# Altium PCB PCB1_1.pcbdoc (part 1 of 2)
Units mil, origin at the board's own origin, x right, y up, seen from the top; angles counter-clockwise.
Board outline 2585 x 2710 mil, 2 copper layers (Top Layer, Bottom Layer); 39 components, 30 nets, 170 pads, 81 vias.
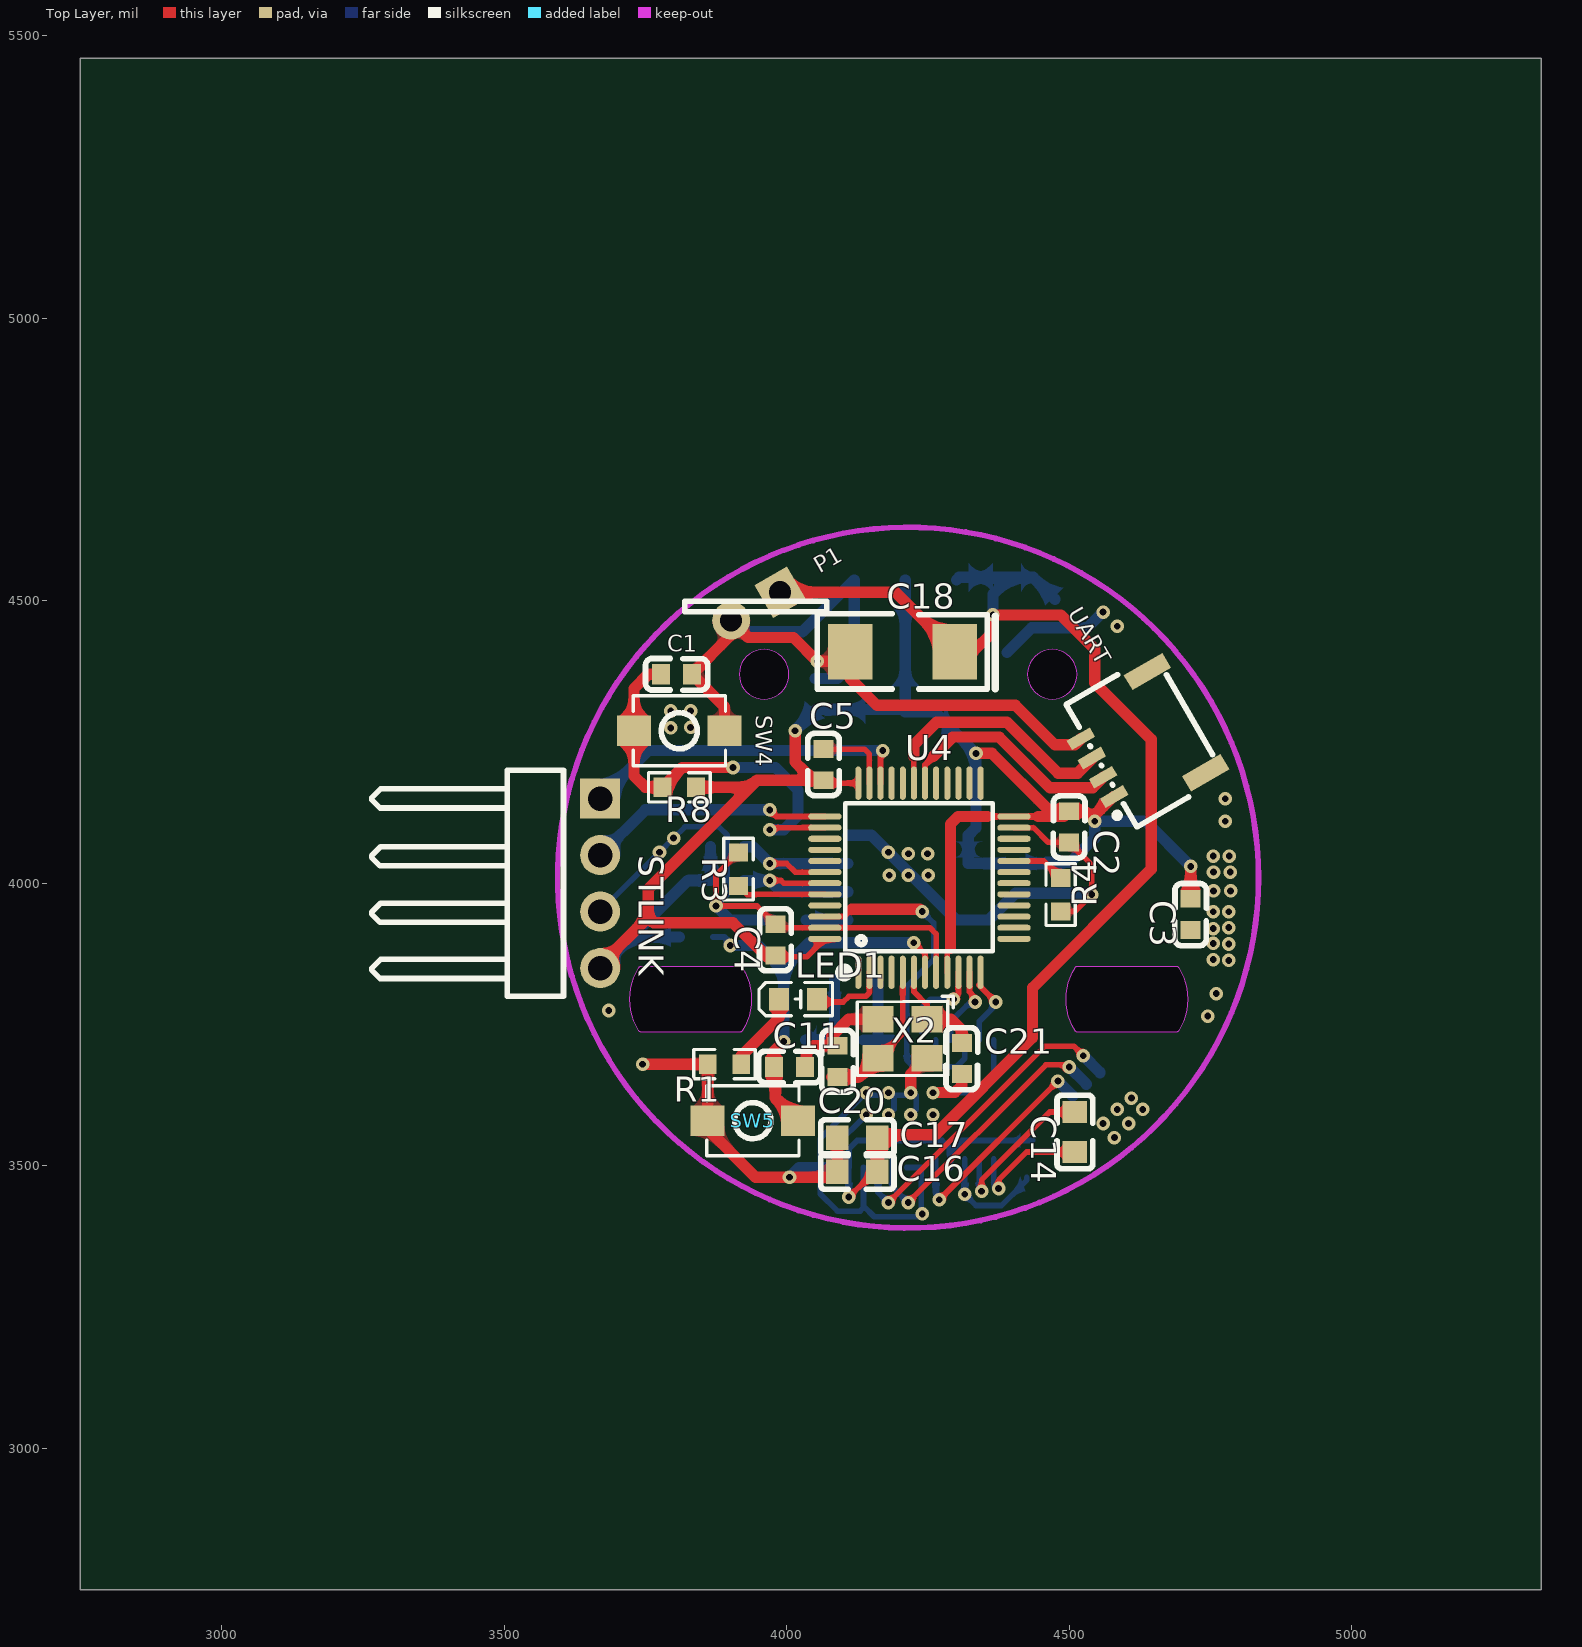
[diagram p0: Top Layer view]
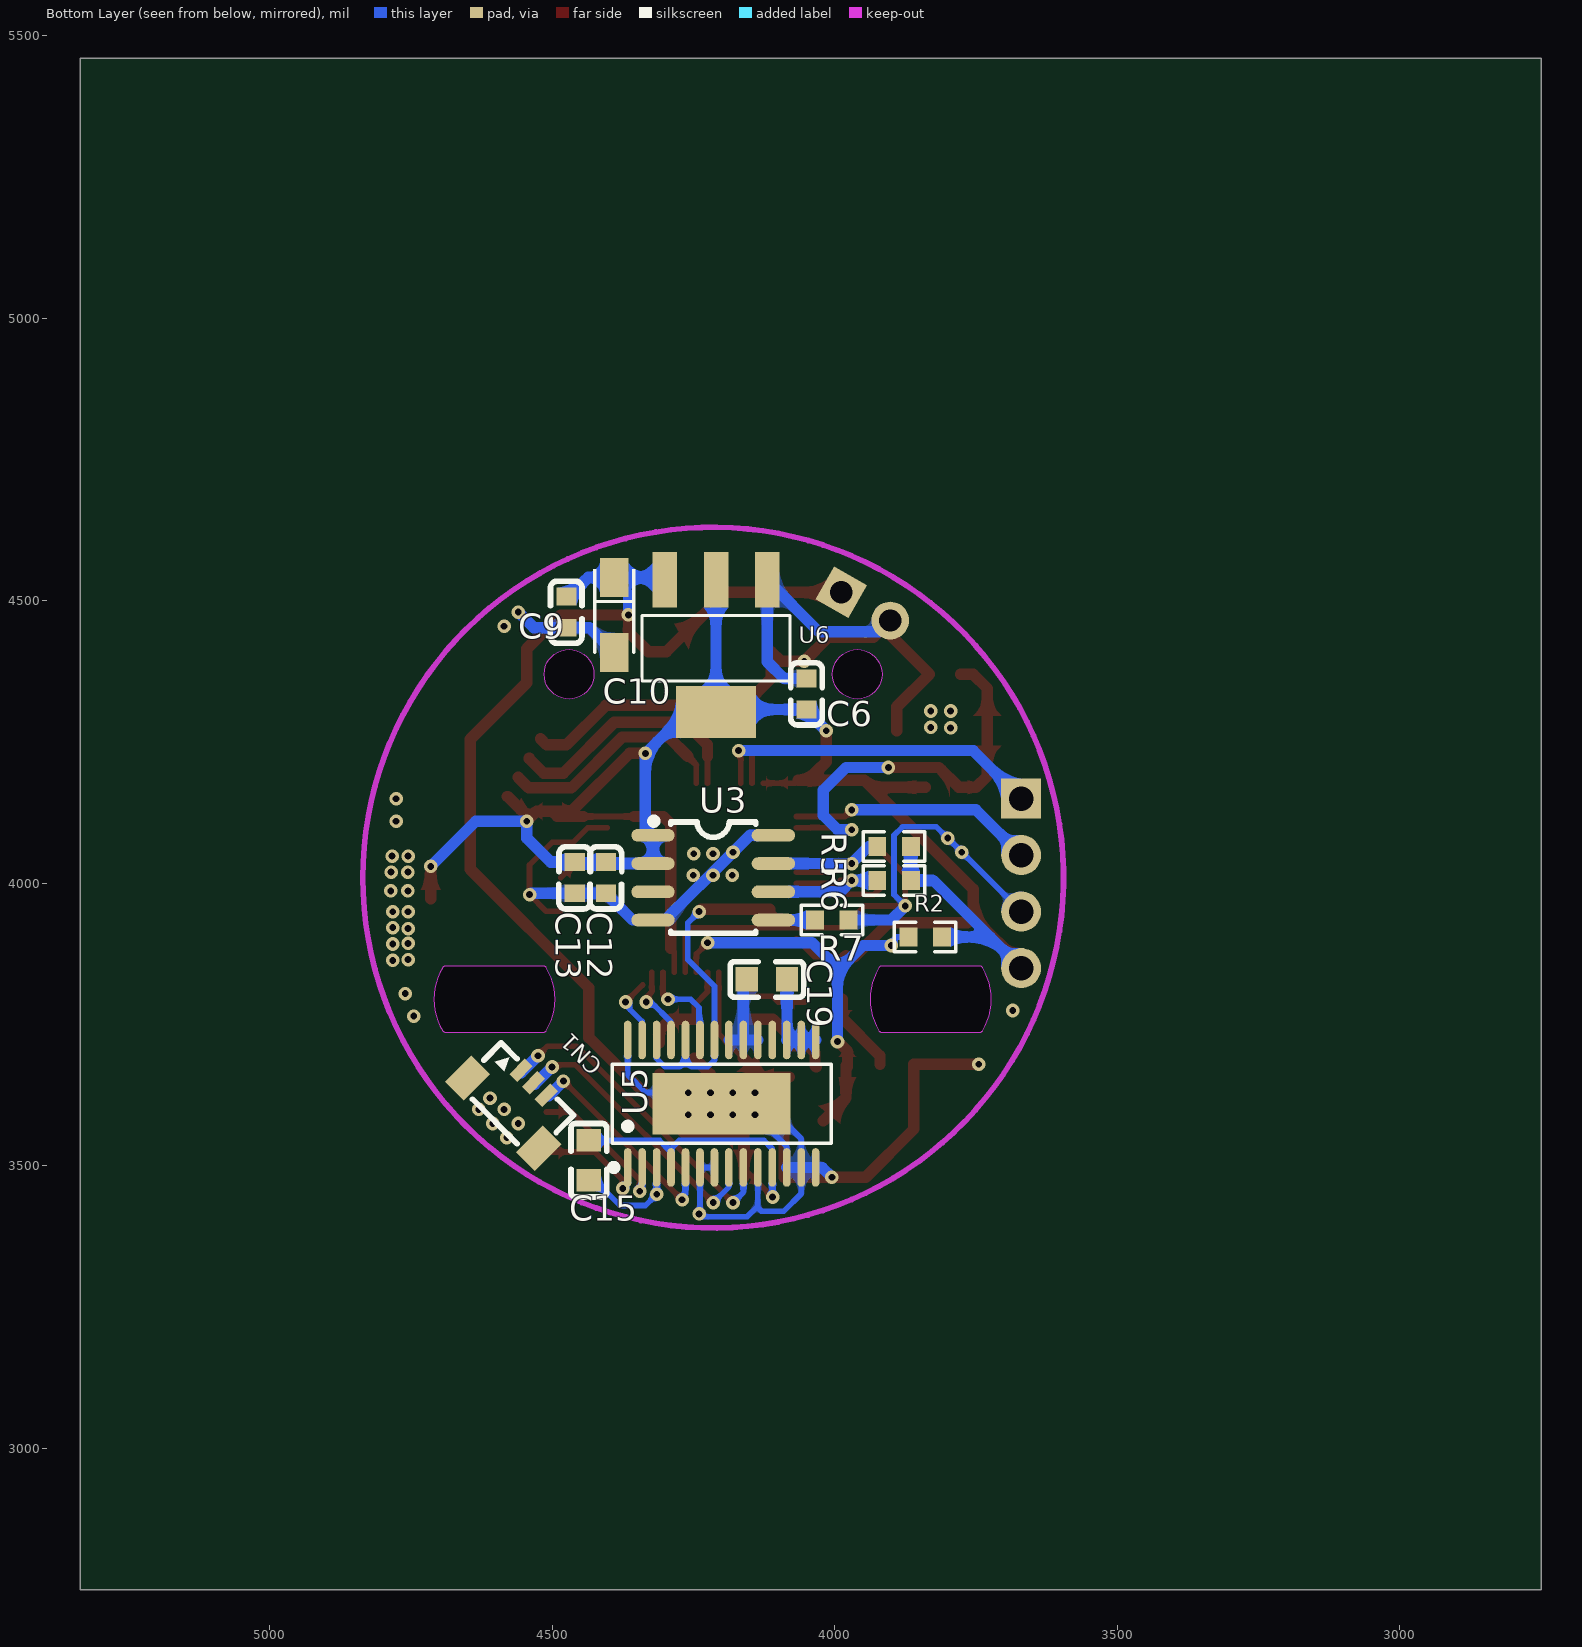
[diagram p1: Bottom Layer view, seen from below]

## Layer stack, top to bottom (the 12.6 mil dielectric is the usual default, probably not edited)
Top Layer: signal copper (thickness not stored)
Dielectric: dielectric 12.6, FR-4, Dk 4.8
Bottom Layer: signal copper (thickness not stored)

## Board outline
5335,2750 2750,2750 2750,5460 5335,5460
cut-out: 4004,4370 ccw(c3960,4370) 3916,4370 ccw(c3960,4370)
cut-out: 4514,4370 ccw(c4470,4370) 4426,4370 ccw(c4470,4370)
cut-out: 4693.77,3739.25 cw(c4689.5,3741.85) 4689.5,3736.85 4514.53,3736.85 cw(c4514.53,3741.85) 4510.26,3739.25 cw(c4602.02,3795) 4494.65,3795 cw(c4602.02,3795) 4510.26,3850.75 cw(c4514.53,3848.15) 4514.53,3853.15 4689.5,3853.15 cw(c4689.5,3848.15) 4693.77,3850.75 cw(c4602.02,3795) 4709.38,3795 cw(c4602.02,3795)
cut-out: 3921.76,3739.25 cw(c3917.48,3741.85) 3917.48,3736.85 3742.52,3736.85 cw(c3742.52,3741.85) 3738.24,3739.25 cw(c3830,3795) 3722.64,3795 cw(c3830,3795) 3738.24,3850.75 cw(c3742.52,3848.15) 3742.52,3853.15 3917.48,3853.15 cw(c3917.48,3848.15) 3921.76,3850.75 cw(c3830,3795) 3937.36,3795 cw(c3830,3795)

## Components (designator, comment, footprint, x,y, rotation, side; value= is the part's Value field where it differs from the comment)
C1 "0603F105M160NT" C0603#1 3805,4370 r180 top
C2 "0603F105M160NT" C0603#1 4500,4100 r90 top
C3 "0603F105M160NT" C0603#1 4715,3945 r90 top
C4 "0603F105M160NT" C0603#1 3980,3900 r270 top
C5 "0603F105M160NT" C0603#1 4065,4210 r270 top
C6 "0.1uf" C0603#1 4050,4335 r270 bottom
C9 "0.1uf" C0603#1 4475,4480 r90 bottom
C10 "10uF" CAP-SMD_L3.2-W1.6-RD 4390,4475 r270 bottom
C11 "0603F105M160NT" C0603#1 4005,3675 r180 top
C12 "0.1uf" C0603#1 4405,4010 r90 bottom
C13 "1uf" C0603#1 4460,4010 r90 bottom
C14 "0.01uF" C0603#2 4510,3560 r270 top
C15 "0.1uF" C0603#2 4435,3510 r270 bottom
C16 "0.1uF" C0603#2 4125,3490 r180 top
C17 "0.1uF" C0603#2 4125,3550 r0 top
C18 "100uF" CAP-SMD_L6.0-W3.2-R-RD 4205,4410 r0 top
C19 "0.47uF" C0603#2 4120,3830 r0 bottom
C20 "0603CG200J101NT" C0603#1 4090,3685 r270 top
C21 "0603CG200J101NT" C0603#1 4310,3690 r90 top
CN1 "X0800WRS-03HF-LPV01" CONN-SMD_X0800WRS-03HF-LPV01 4560,3620 r225 bottom
LED1 "FC-DA1608HRK-620D" LED0603-FD 4020,3795 r180 top
P1 "2.54-1*2P母" HDR-TH_2P-P2.54-V-F 3945,4490 r210 top
R1 "510Ω" R0603 3890,3680 r0 top
R2 "HoLTT0603-1/10W-100KR-1%" R0603 3840,3905 r180 bottom
R3 "10k" R0603 3915,4025 r90 top
R4 "10k" R0603 4485,3980 r90 top
R5 "10k" R0603 3895,4065 r180 bottom
R6 "10k" R0603 3895,4005 r180 bottom
R7 "1k" R0603 4005,3935 r0 bottom
R8 "HoLTT0603-1/10W-100KR-1%" R0603 3810,4170 r0 top
STLINK "2.54-1*4P反弯排针" HDR-TH_4P-P2.54-H-M-W10.4 3670,4000 r270 top
SW4 "KEY-3*4*2" SW-SMD_L4.0-W2.9-LS5.0 3810,4270 r180 top
SW5 "KEY-3*4*2" SW-SMD_L4.0-W2.9-LS5.0 3940,3580 r0 top
U3 "AS5600" SOIC-8_L5.0-W4.0-P1.27-LS6.0-BL 4215,4010 r270 bottom
U4 "STM32F103C8T6" LQFP-48_L7.0-W7.0-P0.50-LS9.0-BL 4235,4010 r0 top
U5 "DRV8313PWPR" HTSSOP-28_L9.8-W4.5-P0.65-LS6.6-BL-EP 4200,3610 r180 bottom
U6 "AMS1117-3.3_C6186" SOT-223-3_L6.5-W3.4-P2.30-LS7.0-BR 4210,4420 r90 bottom
UART "HDGC1002WR-S-4P" CONN-SMD_4P-P1.00_HDGC_HDGC1002WR-S-4P 4620,4245 r120 top
X2 "3225-8.00-10-10-10/A" OSC-SMD_4P-L3.2-W2.5-BL 4205,3725 r180 top

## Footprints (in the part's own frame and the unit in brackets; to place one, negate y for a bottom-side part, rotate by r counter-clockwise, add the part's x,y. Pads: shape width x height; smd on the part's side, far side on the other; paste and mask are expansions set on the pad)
C0603#1 [mm]
  rect 0.8x0.9 smd: 1(-0.7,0) 2(0.7,0)
  silkscreen extent -1.41,-0.71 1.39,0.72
C0603#2 [mm]
  rect 1x1.1 smd: 1(-0.9,0) 2(0.9,0)
  silkscreen extent -1.65,-0.8 1.65,0.8
CAP-SMD_L3.2-W1.6-RD [mil]
  rect 69.19x51.02 smd: 1(-66.39,0) 2(66.39,0)
  silkscreen extent -81,-37 66,37
CAP-SMD_L6.0-W3.2-R-RD [mm]
  rect 2x2.5 smd: 1(2.35,0) 2(-2.35,0)
  silkscreen extent -3.84,-1.68 4.17,1.7
CONN-SMD_4P-P1.00_HDGC_HDGC1002WR-S-4P [mm]
  rect 0.5x1.2 smd: 1(-1.5,2.05) 2(-0.5,2.05) 3(0.5,2.05) 4(1.5,2.05)
  rect 0.8x2 smd: 5(2.625,-2.05) 6(-2.625,-2.05)
  silkscreen extent -3.18,-2.72 3.17,2.48
CONN-SMD_X0800WRS-03HF-LPV01 [mm]
  rect 0.5x1 smd: 1(-0.8,0.972) 2(0,0.972) 3(0.8,0.972)
  rect 1.2x1.7 smd: 4(2.25,-0.95) 5(-2.25,-0.972)
  silkscreen extent -2.3,-1.49 2.3,1.21
HDR-TH_2P-P2.54-V-F [mm]
  rect 1.7x1.7 hole 1: 1(-1.27,0)
  round 1.7 hole 1: 2(1.27,0)
  silkscreen extent -2.88,-1.79 2.88,1.8
HDR-TH_4P-P2.54-H-M-W10.4 [mm]
  rect 1.8x1.8 hole 1.1: 1(-3.81,0)
  round 1.8 hole 1.1: 2(-1.27,0) 3(1.27,0) 4(3.81,0)
  silkscreen extent -5.09,-10.27 5.07,-1.65
HTSSOP-28_L9.8-W4.5-P0.65-LS6.6-BL-EP [mil]
  oval 13.5x68.2 smd: 1(-166.3,-112.8) 2(-140.7,-112.8) 3(-115.2,-112.8) 4(-89.6,-112.8) 5(-64,-112.8) 6(-38.4,-112.8) 7(-12.8,-112.8) 8(12.8,-112.8) 9(38.4,-112.8) 10(64,-112.8) 11(89.6,-112.8) 12(115.2,-112.8) 13(140.8,-112.8) 14(166.3,-112.8) 15(166.3,112.8) 16(140.8,112.8) 17(115.2,112.8) 18(89.6,112.8) 19(64,112.8) 20(38.4,112.8) 21(12.8,112.8) 22(-12.8,112.8) 23(-38.4,112.8) 24(-64,112.8) 25(-89.6,112.8) 26(-115.2,112.8) 27(-140.7,112.8) 28(-166.3,112.8)
  rect 244.1x108.3 smd: 29(0,0)
  silkscreen extent -197,-119 194,70
LED0603-FD [mm]
  rect 0.9x1 smd: 1(-0.85,0) 2(0.85,0)
  silkscreen extent -1.55,-0.75 1.75,0.75
LQFP-48_L7.0-W7.0-P0.50-LS9.0-BL [mm]
  oval 0.27x1.5 smd: 1(-2.75,-4.25) 2(-2.25,-4.25) 3(-1.75,-4.25) 4(-1.25,-4.25) 5(-0.75,-4.25) 6(-0.25,-4.25) 7(0.25,-4.25) 8(0.75,-4.25) 9(1.25,-4.25) 10(1.75,-4.25) 11(2.25,-4.25) 12(2.75,-4.25) 25(2.75,4.25) 26(2.25,4.25) 27(1.75,4.25) 28(1.25,4.25) 29(0.75,4.25) 30(0.25,4.25) 31(-0.25,4.25) 32(-0.75,4.25) 33(-1.25,4.25) 34(-1.75,4.25) 35(-2.25,4.25) 36(-2.75,4.25)
  oval 1.5x0.27 smd: 13(4.25,-2.75) 14(4.25,-2.25) 15(4.25,-1.75) 16(4.25,-1.25) 17(4.25,-0.75) 18(4.25,-0.25) 19(4.25,0.25) 20(4.25,0.75) 21(4.25,1.25) 22(4.25,1.75) 23(4.25,2.25) 24(4.25,2.75) 37(-4.25,2.75) 38(-4.25,2.25) 39(-4.25,1.75) 40(-4.25,1.25) 41(-4.25,0.75) 42(-4.25,0.25) 43(-4.25,-0.25) 44(-4.25,-0.75) 45(-4.25,-1.25) 46(-4.25,-1.75) 47(-4.25,-2.25) 48(-4.25,-2.75)
  silkscreen extent -3.59,-4.46 3.3,3.34
OSC-SMD_4P-L3.2-W2.5-BL [mm]
  rect 1.4x1.2 smd: 1(-1.1,-0.875) 2(1.1,-0.875) 3(1.1,0.875) 4(-1.1,0.875)
  silkscreen extent -2.29,-1.9 2.03,1.65
R0603 [mil]
  rect 31.75x34.02 smd: 1(-29.66,0) 2(29.66,0)
  silkscreen extent -55,-26 55,26
SOIC-8_L5.0-W4.0-P1.27-LS6.0-BL [mil]
  oval 22.38x76.78 smd: 1(-75,-106.5) 2(-25,-106.5) 3(25,-106.5) 4(75,-106.5) 5(75,106.5) 6(25,106.5) 7(-25,106.5) 8(-75,106.5)
  silkscreen extent -106,-111 98,75
SOT-223-3_L6.5-W3.4-P2.30-LS7.0-BR [mm]
  rect 2.5x1.1 smd: 1(2.97,-2.3) 2(2.97,0) 3(2.97,2.3)
  rect 2.34x3.6 smd: 4(-2.97,0)
  silkscreen extent -1.57,-3.33 1.37,3.33
SW-SMD_L4.0-W2.9-LS5.0 [mm]
  rect 1.53x1.36 smd: 1(-2.035,0) 2(2.035,0)
  silkscreen extent -2.08,-1.58 2.08,1.58

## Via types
v1: diameter 24, hole 12.01, Top Layer to Bottom Layer, 73 vias
v2: diameter 23.62, hole 11.81, Top Layer to Bottom Layer, 8 vias

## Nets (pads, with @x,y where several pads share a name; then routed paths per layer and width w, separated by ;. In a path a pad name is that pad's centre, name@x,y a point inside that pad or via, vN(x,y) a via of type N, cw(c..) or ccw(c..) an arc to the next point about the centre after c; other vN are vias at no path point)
$1N6846: LED1.2 R1.2 | length 142.7
  Top Layer w20: R1.2@3919.66,3680 3919.66,3694.66 3986.53,3761.53 LED1.2@3986.53,3795
$1N8586: C14.2 U5.1 | length 226.3
  Top Layer w10: v1(4375,3460) 4375,3475 4424.56,3524.56 C14.2@4510,3524.56
  Bottom Layer w10: U5.1@4366.3,3512.2 4366.3,3468.7 v1(4375,3460)
$1N8587: C14.1 U5.2 | length 293.9
  Top Layer w10: v1(4345,3455) 4345,3475 4465.43,3595.43 C14.1@4510,3595.43
  Bottom Layer w10: U5.2@4340.7,3512.2 4340.7,3459.3 v1(4345,3455)
$1N8589: C15.2 U5.3 | length 203.8
  Bottom Layer w10: U5.3@4315.2,3512.2 4315.2,3450.2 v1(4315,3450) 4335,3430 4380,3430 4425,3475 C15.2@4425,3479.56
$1N8596: C19.1 U5.15 U5.16 U5.17 | length 158.4
  Bottom Layer w20: U5.15@4033.7,3722.8 U5.16@4059.2,3722.8 U5.17@4084.8,3722.8 4084.57,3723.03 C19.1@4084.57,3830
$1N18711: R7.2 U3.5 | length 73.8
  Bottom Layer w20: R7.2@4034.66,3935 U3.5@4108.5,3935
BOOT0: R3.1 U4.44 | length 159.2
  Top Layer w10: R3.1@3915,3995.34 3930.34,3980 3945,3980 3945.47,3980.47 U4.44@4067.68,3980.47
BOOT1: R4.2 U4.20 | length 95.1
  Top Layer w10: U4.20@4402.32,4039.53 4455.13,4039.53 R4.2@4485,4009.66
EN: U4.46 U5.22 U5.24 U5.26 | length 662.2
  Top Layer w10: U4.46@4067.68,3941.1 4102.21,3941.1 4115,3953.89
  Top Layer w20: 4115,3953.89 4236.11,3953.89 v1(4240,3950)
  Bottom Layer w10: v1(4240,3950) 4260,3930 4260,3865 4212.8,3817.8 U5.22@4212.8,3722.8 4212.8,3687.8 4212.5,3687.5 4224.87,3675.13 4253.13,3675.13 4264,3686 ; U5.24@4264,3722.8 4264,3686 ; U5.26@4315.2,3722.8 4315.2,3690.2 4300.13,3675.13 4274.87,3675.13 4264,3686
GND: C1.1 C2.1 C3.1 C4.1 C5.1 C6.1 C9.1 C10.2 C11.1 C12.1 C13.1 C16.2 C17.1 C18.2 C19.2 C20.1 C21.1 P1.2 R1.1 R3.2 R4.1 R7.1 STLINK.3 SW4.1 SW5.1 U3.4 U3.8 U4.8 U4.23 U4.35 U4.47 U5.6 U5.7 U5.10 U5.12 U5.13 U5.14 U5.19 U5.20 U5.21 U5.28 U5.29 U6.1 UART.4 X2.2 X2.4 | length 5997.2
  Top Layer w10: SW5.1@3859.88,3580 SW5.1@3860.34,3580.46 ; R3.2@3915,4054.66 3875,4014.66 v1(3875,3960) 3947.56,3960 C4.1@3980,3927.56 3986.14,3921.42 U4.47@4067.68,3921.42 4253.58,3921.42 4264.53,3910.47 U4.8@4264.53,3842.68 ; v1(4005,3480) v1@4005,3485 ; C5.1@4065,4237.56 4137.44,4237.56 4146.42,4228.58 U4.35@4146.42,4177.32 ; C16.2@4084.56,3490 4085,3489.56 C16.2@4085,3480 ; U4.23@4402.32,4098.58 4436.85,4098.58 4462.99,4072.44 C2.1@4500,4072.44 4540,4032.44 v1(4540,3980) 4510.34,3950.34 R4.1@4485,3950.34
  Top Layer w20: v1(3745,3680) R1.1@3860.34,3680 SW5.1@3860.34,3580.46 ; SW5.1@3859.88,3580 3859.88,3565.12 3945,3480 v1(4005,3480) C16.2@4085,3480 ; SW4.1@3890.12,4270 3890.12,4312.44 C1.1@3832.56,4370 3901.7,4439.14 P1.2@3901.7,4465 3931.7,4435 4011.96,4435 v1(4054,4392.96) 4095.44,4392.96 C18.2@4112.48,4410 4112.48,4362.52 4160,4315 4405,4315 4475,4245 4509.8,4245 UART.4@4520.58,4255.79 ; C11.1@4032.56,3675 4035,3677.44 4035,3700 4047.56,3712.56 4080,3712.56 4080,3730 4109.45,3759.45 X2.2@4161.69,3759.45 ; C16.2@4089.57,3480.01 C17.1@4089.57,3555 ; 4219.7,3629.7 4219.7,3661.94 X2.4@4248.31,3690.55 ; 4259,3629.7 4297.26,3629.7 4310,3642.44 C21.1@4310,3662.44
  Bottom Layer w10: STLINK.3@3670,3950 v1(3775,4055) v1(3800,4080) 3820,4100 3880,4100 3895,4085 3895,3980 v1(3875,3960) ; v1(4005,3480) v1@4005,3485 ; U5.12@4084.8,3497.2 4084.8,3534.2 U5.29@4140.9,3590.3 ; U5.10@4136,3497.2 4136,3429 ; U5.29@4140,3625 U5.29@4185,3625 ; U5.29@4140.9,3629.7 4059.2,3548 U5.13@4059.2,3497.2 4059.2,3450.8 4090,3420 4130,3420 4136,3426 4136,3429 ; U5.29@4180.3,3590.3 4190,3600 U5.29@4190,3625 ; U5.29@4180.3,3629.7 U5.29@4185,3625 ; U5.7@4212.8,3497.2 U5.6@4238.4,3497.2 4238.4,3416.6 v1(4240,3415) 4235,3410 4155,3410 4136,3429 ; U5.29@4219.7,3590.3 4229.4,3600 4229.4,3625 U5.29@4190,3625 ; U5.29@4259,3629.7 4259.3,3630 4335,3630 4366.3,3661.3 U5.28@4366.3,3722.8 ; U5.29@4185,3625 U5.29@4190,3625
  Bottom Layer w20: v1(3875,3960) 3900,3935 R7.1@3975.34,3935 ; P1.2@3901.7,4465 3921.7,4445 4027.52,4445 U6.1@4119.45,4536.93 4119.45,4392.01 4090,4362.56 C6.1@4050,4362.56 ; v1(4005,3480) 4022.2,3497.2 U5.14@4033.7,3497.2 U5.13@4059.2,3497.2 U5.12@4084.8,3497.2 ; v1@4053.47,4392.44 v1(4054,4392.96) ; U3.8@4108.5,4085 4150,4085 v1(4180,4055) 4300,3935 U3.4@4321.5,3935 4357.56,3935 C12.1@4405,3982.44 C13.1@4460,3982.44 4537.56,3982.44 v1(4540,3980) ; U5.19@4136,3722.8 U5.20@4161.6,3722.8 ; C19.2@4155.44,3830 4161.6,3823.84 U5.20@4161.6,3722.8 ; U5.21@4187.2,3722.8 U5.20@4161.6,3722.8 ; C10.2@4390,4408.61 4433.83,4452.44 C9.1@4475,4452.44 4532.44,4452.44 v1(4560,4480)
  other v1: 4580,3550 4560,3575 4605,3575 4585,3600 4630,3600 4610,3620 4745,3765 3685,3775 4760,3805 4782.13,3863.53 4755,3865 4782.13,3892.63 4755,3893.75 4755,3920 4782.13,3921.72 4755,3949.69 4782.13,3949.69 4755.28,3986.62 4785.49,3986.62 4181.39,4014.2 4215.39,4014.2 4250.4,4014.2 4755.28,4020 4785,4020 4755,4048.16 4783.25,4048.16 4215.39,4052.43 4249.38,4052.43 4776.17,4109.89 4776.17,4149.61 3795,4275 3830,4275.93 3795,4305 3830,4305 4585,4455
KEY1: C1.2 R8.1 SW4.2 U4.38 | length 746.8
  Top Layer w10: v1(3970,4095) 3973.58,4098.58 U4.38@4067.68,4098.58
  Top Layer w20: C1.2@3777.44,4370 3755,4370 3729.88,4344.88 SW4.2@3729.88,4270 3729.88,4190.12 3750,4170 R8.1@3780.34,4170 3815.34,4205 v1(3905,4205)
  Bottom Layer w20: v1(3905,4205) 3980,4205 4020,4165 4020,4120 3995,4095 v1(3970,4095)
LED: LED1.1 U4.2 | length 136
  Top Layer w10: LED1.1@4053.46,3790 4100,3790 4110,3800 4140,3800 4146.42,3806.42 U4.2@4146.42,3842.68
OSC_IN: C20.2 U4.5 X2.3 | length 265.7
  Top Layer w10: X2.3@4161.69,3690.55 4205.47,3734.33 U4.5@4205.47,3842.68
  Top Layer w20: C20.2@4080,3657.44 4128.58,3657.44 X2.3@4161.69,3690.55
OSC_OUT: C21.2 U4.6 X2.1 | length 185
  Top Layer w10: U4.6@4225.16,3842.68 4225.16,3808.15 4248.31,3785 X2.1@4248.31,3759.45
  Top Layer w20: X2.1@4248.31,3759.45 4290.55,3759.45 4310,3740 C21.2@4310,3717.56
PWM1: U4.12 U5.27 | length 121.9
  Top Layer w10: U4.12@4339.9,3820.11 v1(4370,3790)
  Bottom Layer w10: U5.27@4340.7,3722.8 4340.7,3755.7 4370,3785 v1(4370,3790)
PWM2: U4.11 U5.25 | length 147.1
  Top Layer w10: U4.11@4323.58,3842.68 4323.58,3808.15 4333.47,3798.26 v1(4333.47,3789.99)
  Bottom Layer w10: U5.25@4289.6,3722.8 4290,3723.2 4290,3755 4324.99,3789.99 v1(4333.47,3789.99)
PWM3: U4.10 U5.23 | length 155.4
  Top Layer w10: v1(4295,3795) 4303.9,3803.9 U4.10@4303.9,3842.68
  Bottom Layer w10: U5.23@4238.4,3737.8 4240,3739.4 4240,3780 4255,3795 v1(4295,3795)
RESET: C11.2 R2.1 SW5.2 U4.7 | length 759.1
  Top Layer w10: v1(4225,3895) 4244.84,3875.16 U4.7@4244.84,3842.68
  Top Layer w20: C11.2@3977.44,3675 3977.44,3703.28 3994.16,3720 v1(3995,3720) ; C11.2@3980,3677.44 3980,3620.12 SW5.2@4020.12,3580
  Bottom Layer w10: R2.1@3869.66,3905 3890,3905 3900,3895 v1(3900,3890)
  Bottom Layer w20: v1(3900,3890) 3950,3890 3995,3845 ; v1(3995,3720) 3995,3845 ; v1(4225,3895) 4040,3895 3995,3850 3995,3845
RX: U4.31 UART.3 | length 448.9
  Top Layer w10: U4.31@4225.16,4177.32 4225.16,4224.84 4225,4225 4225.16,4225
  Top Layer w20: 4225,4225 4225,4245 4265,4285 4390,4285 4480,4195 4515,4195 4540.27,4220.27 UART.3@4540.27,4221.69
SCL: R5.1 U3.7 U4.42 | length 300.2
  Top Layer w10: v1(3970,4035) 4000,4035 4015.16,4019.84 U4.42@4067.68,4019.84
  Bottom Layer w20: R5.1@3924.66,4065 3940,4065 v1(3970,4035) U3.7@4108.5,4035
SDA: R6.1 U3.6 U4.43 | length 291.9
  Top Layer w10: v1(3970,4005) 3990,4005 3995,4000 4067.52,4000 U4.43@4067.68,4000.16
  Bottom Layer w20: R6.1@3924.66,4005 v1(3970,4005) 3990,3985 U3.6@4108.5,3985
SWCLK: STLINK.2 U4.37 | length 435.7
  Top Layer w10: v1(3970,4130) 3981.73,4118.27 U4.37@4067.68,4118.27
  Bottom Layer w20: STLINK.2@3670,4050 3750,4130 v1(3970,4130)
SWDIO: STLINK.1 U4.34 | length 594.5
  Top Layer w10: U4.34@4166.1,4177.32 4166.1,4231.1 v1(4170,4235)
  Bottom Layer w20: STLINK.1@3670,4150 3755,4235 v1(4170,4235)
TX: U4.30 UART.2 | length 413
  Top Layer w10: U4.30@4244.84,4177.32 4244.84,4209.84 4260,4225
  Top Layer w20: 4260,4225 4294.02,4259.02 4375.98,4259.02 4465.98,4169.02 4541.37,4169.02 UART.2@4559.95,4187.6
U: CN1.3 U5.5 | length 408.7
  Top Layer w10: v1(4270,3440) v1(4480,3650)
  Bottom Layer w10: U5.5@4264,3512.2 4264,3450.14 4270,3444.14 v1(4270,3440)
  Bottom Layer w20: v1(4480,3650) 4505.92,3624.08 CN1.3@4506.26,3624.08
V: CN1.2 U5.8 | length 519.5
  Top Layer w10: v1(4215,3435) 4458.76,3678.76 4496.24,3678.76 v1(4500,3675)
  Bottom Layer w10: U5.8@4187.2,3512.2 4187.2,3462.8 v1(4215,3435)
  Bottom Layer w20: v1(4500,3675) 4530.39,3644.61 CN1.2@4530.39,3644.33
VCC: C9.2 C10.1 C15.1 C16.1 C17.2 C18.1 P1.1 U5.4 U5.11 U6.3 | length 2738.3
  Top Layer w10: v1(4110,3445) 4155,3490 C16.1@4160.43,3490
  Top Layer w20: P1.1@3988.3,4515 4192.52,4515 C18.1@4297.52,4410 4330,4410 4365,4445 v1(4365,4475) 4485,4475 4545,4415 4545,4355 4645,4255 4645,4025 4435,3815 4435,3726.97 4263.03,3555 4160.44,3555 C16.1@4160.44,3480.01
  Bottom Layer w10: v1(4110,3445) 4110,3496.8 U5.11@4110.4,3497.2 4110.4,3530.27 4124.98,3544.85 4275.15,3544.85 4289.6,3530.4 U5.4@4289.6,3497.2 4290,3497.6 4290,3525 4309.87,3544.87 4434.44,3544.87 C15.1@4435,3545.43
  Bottom Layer w20: U6.3@4300.55,4536.93 4305.01,4541.39 C10.1@4395,4541.39 ; v1(4365,4475) 4365,4511.39 C10.1@4395,4541.39 ; C9.2@4475,4502.56 4436.17,4541.39 C10.1@4395,4541.39
VCC3V3: C2.2 C3.2 C4.2 C5.2 C6.2 C12.2 C13.2 R2.2 R5.2 R6.2 R8.2 STLINK.4 U3.1 U3.2 U4.9 U4.24 U4.36 U4.48 U6.2 U6.4 UART.1 | length 3725.4
  Top Layer w10: C4.2@3982.56,3870 4035.95,3870 U4.48@4067.68,3901.73 ; C5.2@4065,4182.44 4070.12,4177.32 U4.36@4126.73,4177.32 ; U4.9@4284.21,3842.68 4284.21,3879.21 4290,3885 ; 4355,4118.27 U4.24@4402.32,4118.27 4445,4118.27
  Top Layer w20: STLINK.4@3670,3850 3670,3855 3755,3940 ; R8.2@3839.66,4170 3935,4170 ; C4.2@3980,3872.44 3980.12,3872.44 3982.56,3870 3965,3870 3905,3930 3765,3930 3755,3940 ; v1(4015,4270) 4015,4215 C5.2@4047.56,4182.44 ; C5.2@4065,4182.44 C5.2@4047.56,4182.44 ; 4290,3885 4290,4105 4303.27,4118.27 4355,4118.27 ; v1(4335,4230) 4363.28,4230 4465.72,4127.56 C2.2@4500,4127.56 ; 4445,4118.27 4490.71,4118.27 C2.2@4500,4127.56 ; UART.1@4579.64,4153.5 4578.5,4153.5 4545,4120 v1(4545,4110) 4527.44,4127.56 C2.2@4500,4127.56 ; C3.2@4715,3972.56 v1(4715,4030) ; 3755,3940 3755,3990 3935,4170 ; 3935,4170 3947.44,4182.44 C5.2@4047.56,4182.44
  Bottom Layer w20: STLINK.4@3670,3850 3725,3905 ; R2.2@3810.34,3905 3725,3905 ; R5.2@3865.34,4065 R6.2@3865.34,4005 3825,4005 3725,3905 ; v1(4015,4270) 4052.44,4307.44 4090,4307.44 4205.63,4307.44 U6.4@4210,4303.07 ; U6.2@4210,4536.93 U6.4@4210,4303.07 ; C13.2@4460,4032.56 4457.56,4035 U3.2@4321.5,4035 U3.1@4321.5,4085 4335,4098.5 v1(4335,4230) 4261.93,4303.07 U6.4@4210,4303.07 ; C13.2@4460,4037.56 4502.56,4037.56 4545,4080 v1(4545,4110) 4635,4110 v1(4715,4030)
W: CN1.1 U5.9 | length 594.3
  Top Layer w10: v1(4180,3435) 4457,3712 4508,3712 v1(4525,3695)
  Bottom Layer w10: U5.9@4161.6,3512.2 4161.6,3453.4 v1(4180,3435)
  Bottom Layer w20: v1(4525,3695) 4554.52,3665.48 CN1.1@4554.52,3664.57
"": CN1.4 CN1.5 U3.3 U4.1 U4.3 U4.4 U4.13 U4.14 U4.15 U4.16 U4.17 U4.18 U4.19 U4.21 U4.22 U4.25 U4.26 U4.27 U4.28 U4.29 U4.32 U4.33 U4.39 U4.40 U4.41 U4.45 U5.18 UART.5 UART.6
  other v2: 4140.9,3590.3 4180.3,3590.3 4219.7,3590.3 4259,3590.3 4140.9,3629.7 4180.3,3629.7 4219.7,3629.7 4259,3629.7

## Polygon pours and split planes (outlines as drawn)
GND on Top Layer (solid, remove dead copper, pour order 0): 3085,3000 5085,3000 5085,5100 3085,5100
GND on Bottom Layer (solid, remove dead copper, pour order 1): 3000,3105 5000,3105 5000,5210 3000,5210

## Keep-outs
Board Outline Layer:
  circle w10 net "": c4215,4010 r620
Multi-Layer:
  region net "": 4004,4370 ccw(c3960,4370) 3916,4370 ccw(c3960,4370)
  region net "": 4514,4370 ccw(c4470,4370) 4426,4370 ccw(c4470,4370)
  region net "": 4693.77,3739.25 cw(c4689.5,3741.85) 4689.5,3736.85 4514.53,3736.85 cw(c4514.53,3741.85) 4510.26,3739.25 cw(c4602.02,3795) 4494.65,3795 cw(c4602.02,3795) 4510.26,3850.75 cw(c4514.53,3848.15) 4514.53,3853.15 4689.5,3853.15 cw(c4689.5,3848.15) 4693.77,3850.75 cw(c4602.02,3795) 4709.38,3795 cw(c4602.02,3795)
  region net "": 3921.76,3739.25 cw(c3917.48,3741.85) 3917.48,3736.85 3742.52,3736.85 cw(c3742.52,3741.85) 3738.24,3739.25 cw(c3830,3795) 3722.64,3795 cw(c3830,3795) 3738.24,3850.75 cw(c3742.52,3848.15) 3742.52,3853.15 3917.48,3853.15 cw(c3917.48,3848.15) 3921.76,3850.75 cw(c3830,3795) 3937.36,3795 cw(c3830,3795)

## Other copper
Top Layer:
  region net VCC: 4355,4455 4375,4445 ccw(c4306.83,4445) 4372,4465 4358,4467.86 ccw(c4384.06,4455)
  region net VCC3V3: 4383.66,4113.27 4383.66,4123.27 cw(c4383.66,4240.04) 4362.14,4125.27 4362.14,4111.27 cw(c4383.66,3996.5)
  region net VCC3V3: 4416.34,4123.27 4416.34,4113.27 cw(c4416.34,3996.5) 4437.86,4111.27 4437.86,4125.27 cw(c4416.34,4240.04)
  region net TX: 4241.3,4213.38 4248.38,4206.3 cw(c4285.22,4169.46) 4259.9,4215 4250,4224.9 cw(c4204.46,4250.22)
  region net VCC3V3: 4451.58,4155.84 4458.65,4134.63 4437.44,4141.7
  region net VCC3V3: 4554.14,4143.28 4548.48,4137.33 4546.69,4135.57 4545.5,4134.54 4544.33,4133.65 4543.74,4133.27 4543.15,4132.93 4542.56,4132.64 4541.97,4132.4 4541.37,4132.21 4540.77,4132.08 4540.17,4132.01 4539.57,4132.01 4538.96,4132.07 4538.34,4132.2 4537.72,4132.4 4537.09,4132.68 4536.46,4133.04 4535.82,4133.49 4535.17,4134.01 4534.51,4134.63 4520.37,4120.49 4532.93,4122.07 4568.28,4129.14
  region net VCC3V3: 4065,4192.44 4062.93,4192.51 4060.94,4192.71 4059.01,4193.04 4057.15,4193.49 4055.36,4194.05 4053.62,4194.72 4051.93,4195.49 4050.29,4196.36 4048.16,4197.64 4046.1,4199.07 4043.59,4201.03 4040.17,4204.03 4030.49,4213.65 4016.35,4199.51 4016.82,4199.01 4017.71,4197.92 4018.11,4197.34 4018.47,4196.75 4018.79,4196.16 4019.05,4195.58 4019.25,4195.02 4019.38,4194.5 4019.42,4194.01 4019.38,4193.57 4019.24,4193.19 4019,4192.88 4018.64,4192.64 4018.17,4192.49 4017.56,4192.44
  region net EN: 4118.54,3950.36 4111.46,3957.43 cw(c4101.74,3967.15) 4105,3953.79 4114.9,3943.89 cw(c4128.26,3940.63)
  region net VCC3V3: 3900.86,4160 3901.54,4159.98 3902.95,4159.84 3903.64,4159.71 3904.32,4159.55 3904.96,4159.36 3905.55,4159.13 3906.08,4158.88 3906.55,4158.6 3906.92,4158.28 3907.2,4157.94 3907.38,4157.58 3907.42,4157.18 3907.34,4156.76 3907.11,4156.32 3906.72,4155.86 3940.37,4189.51 3938.86,4188.1 3937.3,4186.83 3935.7,4185.7 3934.07,4184.69 3932.4,4183.82 3930.69,4183.05 3928.94,4182.4 3927.16,4181.84 3924.74,4181.24 3922.26,4180.78 3919.09,4180.38 3915.19,4180.1 3903.66,4179.99 3900.86,4180
  region net VCC3V3: 3745,3970 3744.94,3968.12 3744.77,3966.14 3744.37,3963.35 3743.61,3959.69 3742.6,3955.87 3741.09,3951.2 3739.29,3946.51 3737.24,3941.92 3735.01,3937.54 3733.03,3934.13 3730.97,3931.01 3729.28,3928.75 3728,3927.23 3726.72,3925.86 3740.86,3911.72 3742.14,3913.08 3743.9,3915.25 3747.5,3920.24 3748.92,3922.08 3749.86,3923.13 3750.33,3923.59 3750.81,3924 3751.28,3924.35 3751.77,3924.65 3752.26,3924.89 3752.76,3925.06 3753.27,3925.15 3753.8,3925.18 3754.33,3925.13 3754.89,3924.99 3755.46,3924.77 3756.04,3924.45 3756.65,3924.05 3757.28,3923.54 3757.93,3922.93 3772.07,3937.07 3770.86,3938.37 3769.78,3939.69 3768.84,3941.03 3768.02,3942.4 3767.32,3943.79 3766.72,3945.2 3766.22,3946.64 3765.82,3948.1 3765.49,3949.58 3765.17,3951.6 3764.92,3954.19 3764.81,3957.39 3764.99,3968.2 3765,3970
  region net VCC: 4125.09,3453.02 4118.02,3460.09 4117.6,3459.7 4117.15,3459.35 4116.67,3459.02 4116.17,3458.73 4115.64,3458.46 4114.54,3458 4113.38,3457.63 4112.19,3457.35 4111,3457.15 4109.25,3456.98 4121.98,3444.25 4122.15,3446 4122.35,3447.19 4122.63,3448.38 4123,3449.54 4123.46,3450.64 4123.73,3451.17 4124.02,3451.67 4124.35,3452.15 4124.7,3452.6
  region net W: 4516.98,3710.09 4509.91,3703.02 4510.3,3702.6 4510.65,3702.15 4510.98,3701.67 4511.27,3701.17 4511.54,3700.64 4512,3699.54 4512.37,3698.38 4512.65,3697.19 4512.85,3696 4513.02,3694.25 4525.75,3706.98 4524,3707.15 4522.81,3707.35 4521.62,3707.63 4520.46,3708 4519.36,3708.46 4518.83,3708.73 4518.33,3709.02 4517.85,3709.35 4517.4,3709.7
  region net V: 4483.66,3683.76 4483.66,3673.76 4484.22,3673.7 4484.78,3673.51 4485.34,3673.21 4485.9,3672.82 4486.47,3672.35 4487.59,3671.23 4489.73,3668.66 4491.19,3666.89 4491.64,3666.41 4492.06,3666 4492.06,3684 4491.51,3683.55 4490.99,3683.22 4490.5,3682.98 4490.04,3682.83 4489.58,3682.75 4489.14,3682.74 4488.69,3682.79 4488.24,3682.87 4486.8,3683.28 4485.69,3683.55 4485.07,3683.66 4484.39,3683.74
  region net U: 4464.91,3641.98 4471.98,3634.91 4472.4,3635.3 4472.85,3635.65 4473.33,3635.98 4473.83,3636.27 4474.36,3636.54 4475.46,3637 4476.62,3637.37 4477.81,3637.65 4479,3637.85 4480.75,3638.02 4468.02,3650.75 4467.85,3649 4467.65,3647.81 4467.37,3646.62 4467,3645.46 4466.54,3644.36 4466.27,3643.83 4465.98,3643.33 4465.65,3642.85 4465.3,3642.4
  region net V: 4230.09,3443.02 4223.02,3450.09 4222.6,3449.7 4222.15,3449.35 4221.67,3449.02 4221.17,3448.73 4220.64,3448.46 4219.54,3448 4218.38,3447.63 4217.19,3447.35 4216,3447.15 4214.25,3446.98 4226.98,3434.25 4227.15,3436 4227.35,3437.19 4227.63,3438.38 4228,3439.54 4228.46,3440.64 4228.73,3441.17 4229.02,3441.67 4229.35,3442.15 4229.7,3442.6
  region net W: 4195.09,3443.02 4188.02,3450.09 4187.6,3449.7 4187.15,3449.35 4186.67,3449.02 4186.17,3448.73 4185.64,3448.46 4184.54,3448 4183.38,3447.63 4182.19,3447.35 4181,3447.15 4179.25,3446.98 4191.98,3434.25 4192.15,3436 4192.35,3437.19 4192.63,3438.38 4193,3439.54 4193.46,3440.64 4193.73,3441.17 4194.02,3441.67 4194.35,3442.15 4194.7,3442.6
  region net $1N8586: 4380,3475 4370,3475 4369.98,3474.45 4369.91,3473.92 4369.8,3473.42 4369.66,3472.94 4369.48,3472.48 4369.26,3472.03 4369.02,3471.6 4368.46,3470.78 4367.81,3469.97 4366,3467.94 4384,3467.94 4382.19,3469.97 4381.54,3470.78 4380.98,3471.6 4380.74,3472.03 4380.52,3472.48 4380.34,3472.94 4380.2,3473.42 4380.09,3473.92 4380.02,3474.45
  region net $1N8587: 4350,3471.34 4340,3471.34 4339.98,3470.77 4339.91,3470.2 4339.8,3469.63 4339.66,3469.07 4339.48,3468.51 4339.02,3467.4 4338.46,3466.32 4337.81,3465.28 4337.11,3464.3 4336,3462.94 4354,3462.94 4352.89,3464.3 4352.19,3465.28 4351.54,3466.32 4350.98,3467.4 4350.52,3468.51 4350.34,3469.07 4350.2,3469.63 4350.09,3470.2 4350.02,3470.77
  region net U: 4285.09,3448.02 4278.02,3455.09 4277.6,3454.7 4277.15,3454.35 4276.67,3454.02 4276.17,3453.73 4275.64,3453.46 4274.54,3453 4273.38,3452.63 4272.19,3452.35 4271,3452.15 4269.25,3451.98 4281.98,3439.25 4282.15,3441 4282.35,3442.19 4282.63,3443.38 4283,3444.54 4283.46,3445.64 4283.73,3446.17 4284.02,3446.67 4284.35,3447.15 4284.7,3447.6
  region net SDA: 3986.34,4000 3986.34,4010 3985.77,4010.02 3985.2,4010.09 3984.63,4010.2 3984.07,4010.34 3983.51,4010.52 3982.4,4010.98 3981.32,4011.54 3980.28,4012.19 3979.3,4012.89 3977.94,4014 3977.94,3996 3979.3,3997.11 3980.28,3997.81 3981.32,3998.46 3982.4,3999.02 3983.51,3999.48 3984.07,3999.66 3984.63,3999.8 3985.2,3999.91 3985.77,3999.98
  region net SCL: 3986.34,4030 3986.34,4040 3985.77,4040.02 3985.2,4040.09 3984.63,4040.2 3984.07,4040.34 3983.51,4040.52 3982.4,4040.98 3981.32,4041.54 3980.28,4042.19 3979.3,4042.89 3977.94,4044 3977.94,4026 3979.3,4027.11 3980.28,4027.81 3981.32,4028.46 3982.4,4029.02 3983.51,4029.48 3984.07,4029.66 3984.63,4029.8 3985.2,4029.91 3985.77,4029.98
  region net SWDIO: 4161.1,4218.66 4171.1,4218.66 4171.17,4219.22 4171.36,4219.79 4171.66,4220.35 4172.06,4220.92 4172.53,4221.48 4173.08,4222.04 4174.31,4223.14 4177.54,4225.71 4178.59,4226.63 4179,4227.06 4161,4227.06 4161.45,4226.5 4161.79,4225.98 4162.03,4225.49 4162.17,4225.02 4162.24,4224.57 4162.24,4224.13 4162.18,4223.69 4162.08,4223.25 4161.63,4221.82 4161.33,4220.71 4161.21,4220.09 4161.13,4219.41
  region net KEY1: 3986.34,4093.58 3986.34,4103.58 3985.62,4103.56 3984.96,4103.49 3983.77,4103.28 3982.24,4102.9 3981.77,4102.81 3981.31,4102.74 3980.86,4102.72 3980.4,4102.74 3979.95,4102.83 3979.48,4102.99 3978.99,4103.23 3978.48,4103.56 3977.94,4104 3977.94,4086 3978.35,4086.4 3979.26,4087.4 3981.87,4090.5 3982.99,4091.68 3983.55,4092.2 3984.12,4092.66 3984.68,4093.04 3985.24,4093.33 3985.79,4093.52
  region net SWCLK: 3978.02,4114.91 3985.09,4121.98 3984.7,4122.4 3984.35,4122.85 3984.02,4123.33 3983.73,4123.83 3983.46,4124.36 3983,4125.46 3982.63,4126.62 3982.35,4127.81 3982.15,4129 3981.98,4130.75 3969.25,4118.02 3971,4117.85 3972.19,4117.65 3973.38,4117.37 3974.54,4117 3975.64,4116.54 3976.17,4116.27 3976.67,4115.98 3977.15,4115.65 3977.6,4115.3
  region net RESET: 4233.02,3879.91 4240.09,3886.98 4239.7,3887.4 4239.35,3887.85 4239.02,3888.33 4238.73,3888.83 4238.46,3889.36 4238,3890.46 4237.63,3891.62 4237.35,3892.81 4237.15,3894 4236.98,3895.75 4224.25,3883.02 4226,3882.85 4227.19,3882.65 4228.38,3882.37 4229.54,3882 4230.64,3881.54 4231.17,3881.27 4231.67,3880.98 4232.15,3880.65 4232.6,3880.3
  region net PWM2: 4329.59,3809.22 4322.52,3802.14 4322.94,3801.61 4323.22,3800.99 4323.38,3800.29 4323.44,3799.54 4323.4,3798.73 4323.29,3797.89 4322.91,3796.1 4321.93,3792.46 4321.58,3790.76 4321.5,3789.97 4321.5,3789.24 4334.22,3801.97 4333.35,3802.25 4332.66,3802.91 4332.1,3803.85 4331.62,3804.96 4330.73,3807.32 4330.21,3808.38
  region net PWM3: 4307.44,3800.36 4300.36,3807.44 4299.61,3806.81 4298.93,3806.49 4298.29,3806.4 4297.64,3806.48 4296.18,3806.83 4295.29,3806.96 4294.25,3806.98 4306.98,3794.25 4306.99,3794.79 4306.96,3795.29 4306.91,3795.75 4306.74,3796.57 4306.48,3797.64 4306.42,3797.96 4306.4,3798.29 4306.42,3798.61 4306.49,3798.93 4306.62,3799.26 4306.81,3799.61 4307.08,3799.98
  region net VCC: 4062.72,4505 4051.17,4525 cw(c4051.17,4582.32) 4012.51,4540 4011.93,4490 cw(c4062.72,4411.52)
  region net RESET: 3987.07,3627.19 3972.93,3613.05 cw(c3931.51,3571.63) 3990,3574.76 4028.7,3606.77 cw(c4037.75,3677.87)
  region net KEY1: 3739.88,4326.77 3719.88,4326.77 cw(c3682.38,4326.77) 3704.88,4296.77 3754.88,4296.77 cw(c3777.38,4326.77)
  region net KEY1: 3719.88,4213.23 3739.88,4213.23 cw(c3777.38,4213.23) 3754.88,4243.23 3704.88,4243.23 cw(c3682.38,4213.23)
  region net VCC3V3: 4465.72,4137.56 4465.72,4117.56 cw(c4465.72,4090.83) 4482.28,4111.81 4482.28,4143.31 cw(c4465.72,4164.29)
  region net VCC3V3: 4527.44,4117.56 4527.44,4137.56 cw(c4527.44,4148.66) 4517.72,4143.31 4517.72,4111.81 cw(c4527.44,4106.46)
  region net VCC: 4210.12,3545 4210.12,3565 cw(c4210.13,3779.39) 4180.12,3567.11 4180.12,3530 cw(c4210.12,3507.5)
  region net VCC: 4150.44,3498.35 4170.44,3498.35 cw(c4221.75,3498.35) 4180.12,3528.35 4140.76,3528.35 cw(c4099.13,3498.35)
  region net $1N8586: 4473.35,3529.56 4473.35,3519.56 cw(c4473.35,3500.81) 4488.35,3512.06 4488.35,3537.06 cw(c4473.35,3548.31)
  region net $1N8587: 4473.35,3600.43 4473.35,3590.43 cw(c4473.35,3571.68) 4488.35,3582.93 4488.35,3607.93 cw(c4473.35,3619.18)
  region net BOOT1: 4465.59,4036.14 4457.39,4030.2 cw(c4430.87,4003.69) 4467.99,4008.99 4486.8,4025.54 cw(c4492.11,4062.66)
  region net VCC: 4170.44,3541.65 4150.44,3541.65 cw(c3936.05,3541.65) 4148.33,3511.65 4172.55,3511.65 cw(c4384.83,3541.65)
  region net VCC: 4130.14,3472.21 4130.14,3458.07 cw(c4155.68,3432.52) 4151.02,3468.35 4140.74,3493.42 cw(c4103.62,3498.73)
  region net OSC_OUT: 4320,3740 4300,3740 cw(c4288.33,3740) 4297.89,3733.31 4322.11,3733.31 cw(c4331.67,3740)
  region net VCC3V3: 4537.93,4127.07 4562.3,4123.16 ccw(c4556.01,4129.46) 4564.1,4133.17 4554.26,4150.21 cw(c4479.05,4185.95)
  region net VCC3V3: 4725,4018.31 4705,4018.31 cw(c4642.83,4018.31) 4697.28,3988.31 4732.72,3988.31 cw(c4787.17,4018.31)
  region net VCC3V3: 3708.68,3879.54 3694.54,3893.68 3693.2,3892.45 3691.79,3891.35 3690.33,3890.38 3688.8,3889.53 3687.23,3888.79 3685.6,3888.15 3683.94,3887.6 3681.37,3886.94 3678.73,3886.43 3675.13,3885.94 3667.78,3885.36 3705.36,3847.78 3705.44,3849.85 3705.38,3852.44 3705.17,3854.85 3704.77,3857.63 3703.64,3863.53 3703.29,3865.76 3703.18,3867.06 3703.15,3867.92 3703.16,3868.77 3703.22,3869.62 3703.34,3870.47 3703.52,3871.32 3703.76,3872.18 3704.08,3873.04 3704.47,3873.92 3704.94,3874.81 3705.49,3875.71 3706.14,3876.63 3706.88,3877.58 3708.19,3879.04
  region net VCC3V3: 4044.69,3885.81 4058.83,3885.81 4059.98,3886.89 4061.21,3887.9 4062.51,3888.85 4063.87,3889.74 4065.77,3890.82 4067.75,3891.79 4069.82,3892.65 4072.49,3893.6 4075.23,3894.39 4078.59,3895.15 4081.98,3895.72 4085.91,3896.17 4089.76,3896.38 4091.89,3896.41 4044.69,3896.41 4045.6,3896.34 4046.36,3896.11 4046.98,3895.76 4047.45,3895.29 4047.79,3894.71 4048.01,3894.05 4048.1,3893.31 4048.08,3892.52 4047.96,3891.68 4047.73,3890.81 4047.42,3889.93 4047.02,3889.05 4046.53,3888.18 4045.98,3887.34 4045.36,3886.55
  region net EN: 4102.21,3936.1 4102.21,3946.1 4091.89,3946.41 4091.89,3935.78
  region net BOOT0: 4026.66,3985.47 4026.66,3975.47 4027.35,3975.52 4028.1,3975.68 4029.78,3976.2 4033.43,3977.58 4035.19,3978.14 4036.02,3978.33 4036.78,3978.43 4037.48,3978.41 4038.1,3978.27 4038.62,3977.99 4039.03,3977.54 4039.03,3983.4 4038.62,3982.95 4038.1,3982.67 4037.48,3982.53 4036.78,3982.51 4036.02,3982.61 4035.19,3982.8 4033.43,3983.36 4029.78,3984.74 4028.1,3985.26 4027.35,3985.42
  region net SDA: 4026.27,4005 4027.19,3995 4027.86,3995.05 4028.59,3995.2 4029.38,3995.43 4032.82,3996.72 4034.56,3997.36 4035.39,3997.62 4036.18,3997.8 4036.92,3997.9 4037.6,3997.89 4038.21,3997.77 4038.72,3997.5 4039.14,3997.07 4038.93,4002.93 4038.53,4002.46 4038.01,4002.17 4037.39,4002.02 4036.68,4002 4035.89,4002.09 4035.05,4002.28 4033.23,4002.85 4029.46,4004.26 4027.74,4004.79 4026.97,4004.94
  region net SCL: 4026.66,4024.84 4026.66,4014.84 4027.35,4014.89 4028.1,4015.05 4029.78,4015.57 4033.43,4016.95 4035.19,4017.51 4036.02,4017.7 4036.78,4017.8 4037.48,4017.78 4038.1,4017.64 4038.62,4017.36 4039.03,4016.91 4039.03,4022.77 4038.62,4022.32 4038.1,4022.04 4037.48,4021.9 4036.78,4021.88 4036.02,4021.98 4035.19,4022.17 4033.43,4022.73 4029.78,4024.11 4028.1,4024.63 4027.35,4024.79
  region net KEY1: 4026.66,4103.58 4026.66,4093.58 4043.47,4093.26 4043.47,4103.9
  region net SWCLK: 4026.66,4123.27 4026.66,4113.27 4027.35,4113.32 4028.1,4113.48 4029.78,4114 4033.43,4115.38 4035.19,4115.94 4036.02,4116.13 4036.78,4116.23 4037.48,4116.21 4038.1,4116.07 4038.62,4115.79 4039.03,4115.34 4039.03,4121.2 4038.62,4120.75 4038.1,4120.47 4037.48,4120.33 4036.78,4120.31 4036.02,4120.41 4035.19,4120.6 4033.43,4121.16 4029.78,4122.54 4028.1,4123.06 4027.35,4123.22
  region net VCC3V3: 4106.41,4182.32 4106.41,4172.32 4111.26,4172.24 4113.22,4172.09 4114.46,4171.92 4115.63,4171.69 4116.73,4171.38 4117.24,4171.2 4117.74,4170.99 4118.2,4170.75 4118.65,4170.49 4119.06,4170.2 4119.45,4169.88 4119.8,4169.54 4120.13,4169.16 4120.42,4168.74 4120.67,4168.3 4120.89,4167.81 4121.08,4167.3 4121.22,4166.74 4121.33,4166.14 4121.39,4165.5 4121.41,4164.82 4121.41,4189.82 4121.39,4189.14 4121.33,4188.5 4121.22,4187.9 4121.08,4187.34 4120.89,4186.83 4120.67,4186.34 4120.42,4185.9 4120.13,4185.48 4119.8,4185.1 4119.45,4184.76 4119.06,4184.44 4118.65,4184.15 4118.2,4183.89 4117.74,4183.65 4117.24,4183.44 4116.73,4183.26 4115.63,4182.95 4114.46,4182.72 4113.22,4182.55 4111.26,4182.4
  region net SWDIO: 4171.1,4218.34 4161.1,4218.34 4161.15,4217.65 4161.31,4216.9 4161.83,4215.22 4163.21,4211.57 4163.77,4209.81 4163.96,4208.98 4164.06,4208.22 4164.04,4207.52 4163.9,4206.9 4163.62,4206.38 4163.17,4205.97 4169.03,4205.97 4168.58,4206.38 4168.3,4206.9 4168.16,4207.52 4168.14,4208.22 4168.24,4208.98 4168.43,4209.81 4168.99,4211.57 4170.37,4215.22 4170.89,4216.9 4171.05,4217.65
  region net RX: 4230.16,4218.34 4220.16,4218.34 4220.21,4217.65 4220.37,4216.9 4220.89,4215.22 4222.27,4211.57 4222.83,4209.81 4223.02,4208.98 4223.12,4208.22 4223.1,4207.52 4222.96,4206.9 4222.68,4206.38 4222.23,4205.97 4228.09,4205.97 4227.64,4206.38 4227.36,4206.9 4227.22,4207.52 4227.2,4208.22 4227.3,4208.98 4227.49,4209.81 4228.05,4211.57 4229.43,4215.22 4229.95,4216.9 4230.11,4217.65
  region net TX: 4249.84,4209.84 4239.84,4209.84 4239.97,4209.33 4240.32,4208.78 4241.29,4207.68 4241.74,4207.16 4242.05,4206.69 4242.14,4206.29 4241.91,4205.97 4247.77,4205.97 4247.63,4206.69 4248.39,4207.68 4249.36,4208.78
  region net VCC3V3: 4361.3,4123.27 4361.3,4113.27 4361.99,4113.32 4362.74,4113.48 4364.42,4114 4368.07,4115.38 4369.83,4115.94 4370.66,4116.13 4371.42,4116.23 4372.12,4116.21 4372.74,4116.07 4373.26,4115.79 4373.67,4115.34 4373.67,4121.2 4373.26,4120.75 4372.74,4120.47 4372.12,4120.33 4371.42,4120.31 4370.66,4120.41 4369.83,4120.6 4368.07,4121.16 4364.42,4122.54 4362.74,4123.06 4361.99,4123.22
  region net VCC3V3: 4443.34,4113.27 4443.34,4123.27 4442.65,4123.22 4441.9,4123.06 4440.22,4122.54 4436.57,4121.16 4434.81,4120.6 4433.98,4120.41 4433.22,4120.31 4432.52,4120.33 4431.9,4120.47 4431.38,4120.75 4430.97,4121.2 4430.97,4115.34 4431.38,4115.79 4431.9,4116.07 4432.52,4116.21 4433.22,4116.23 4433.98,4116.13 4434.81,4115.94 4436.57,4115.38 4440.22,4114 4441.9,4113.48 4442.65,4113.32
  region net BOOT1: 4443.34,4034.53 4443.34,4044.53 4442.65,4044.48 4441.9,4044.32 4440.22,4043.8 4436.57,4042.42 4434.81,4041.86 4433.98,4041.67 4433.22,4041.57 4432.52,4041.59 4431.9,4041.73 4431.38,4042.01 4430.97,4042.46 4430.97,4036.6 4431.38,4037.05 4431.9,4037.33 4432.52,4037.47 4433.22,4037.49 4433.98,4037.39 4434.81,4037.2 4436.57,4036.64 4440.22,4035.26 4441.9,4034.74 4442.65,4034.58
  region net PWM2: 4318.58,3808.15 4328.58,3808.15 4328.9,3818.47 4318.27,3818.47
  region net PWM3: 4298.9,3803.9 4308.9,3803.9 4309.22,3818.47 4298.59,3818.47
  region net VCC3V3: 4289.21,3879.21 4279.21,3879.21 4279.38,3878.26 4279.8,3877.18 4280.97,3874.88 4281.47,3873.77 4281.77,3872.77 4281.75,3871.94 4281.28,3871.33 4287.14,3871.33 4286.67,3871.94 4286.65,3872.77 4286.95,3873.77 4288.05,3876.04 4288.62,3877.18 4289.04,3878.26
  region net RESET: 4249.84,3875.16 4239.84,3875.16 4239.52,3866.89 4250.15,3866.89
  region net OSC_OUT: 4220.16,3808.15 4230.16,3808.15 4230.48,3818.47 4219.85,3818.47
  region net OSC_IN: 4200.47,3801.66 4210.47,3801.66 4210.78,3818.47 4200.15,3818.47
  region net LED: 4141.42,3806.42 4151.42,3806.42 4151.73,3818.47 4141.1,3818.47
  region net OSC_IN: 4199.86,3721.64 4188.85,3724.78 cw(c4162.33,3751.3) 4167.63,3714.17 4189.25,3700.43 cw(c4226.37,3695.13)
  region net OSC_IN: 4121.51,3664.51 4135.65,3650.37 cw(c4175.74,3610.28) 4173.42,3666.93 4134.13,3698.35 cw(c4090.77,3695.25)
  region net OSC_OUT: 4290.55,3749.45 4290.55,3769.45 cw(c4290.55,3784.17) 4275.87,3783.07 4275.87,3735.83 cw(c4290.55,3734.73)
  region net VCC: 4241.24,4480.43 4236.94,4456.44 cw(c4183.9,4403.41) 4258.15,4414.01 4283.66,4459.21 cw(c4294.27,4533.46)
  region net VCC3V3: 4097.72,4172.32 4097.72,4182.32 cw(c4097.72,4201.07) 4082.72,4189.82 4082.72,4166.69 cw(c4097.72,4149.52)
  region net VCC3V3: 4017.28,4192.44 4017.28,4172.44 cw(c4017.28,3958.05) 4047.28,4170.33 4047.28,4194.55 cw(c4017.28,4406.83)
  region net OSC_IN: 4128.58,3647.44 4128.58,3667.44 cw(c4128.58,3708.18) 4107.72,3673.19 4107.72,3641.69 cw(c4128.58,3606.7)
  region net VCC3V3: 4012.72,3865 4012.72,3875 cw(c4012.72,3893.75) 3997.72,3882.5 3997.72,3857.5 cw(c4012.72,3846.25)
  region net KEY1: 3817.43,4192.95 3804.42,4208.22 ccw(c3824.3,4188.34) 3796.22,4187.01 3796.22,4152.99 cw(c3872.02,4138.35)
  region net KEY1: 3750,4180 3750,4160 cw(c3750,4109.35) 3764.46,4157.89 3764.46,4182.11 cw(c3750,4230.65)
  region net VCC3V3: 3885.54,4160 3885.54,4180 cw(c3885.54,4394.39) 3855.54,4182.11 3855.54,4157.89 cw(c3885.54,3945.61)
  region net RESET: 3987.44,3703.28 3967.44,3703.28 cw(c3954.85,3703.28) 3961.69,3692.72 3993.19,3692.72 cw(c4000.03,3703.28)
  region net RESET: 3970,3627.28 3990,3627.28 cw(c4132.75,3627.28) 3993.19,3657.28 3961.69,3657.28 cw(c3911.68,3627.28)
  region net $1N6846: 3976.53,3761.53 3996.53,3761.53 cw(c4012.7,3761.53) 4004.24,3775.32 3968.82,3775.32 cw(c3960.36,3761.53)
  region net LED: 4086.18,3785 4086.18,3795 cw(c4086.18,3813.75) 4071.18,3802.5 4071.18,3777.5 cw(c4086.18,3766.25)
  region net PWM1: 4361.98,3805.09 4354.91,3798.02 4355.3,3797.6 4355.65,3797.15 4355.98,3796.67 4356.27,3796.17 4356.54,3795.64 4357,3794.54 4357.37,3793.38 4357.65,3792.19 4357.85,3791 4358.02,3789.25 4370.75,3801.98 4369,3802.15 4367.81,3802.35 4366.62,3802.63 4365.46,3803 4364.36,3803.46 4363.83,3803.73 4363.33,3804.02 4362.85,3804.35 4362.4,3804.7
